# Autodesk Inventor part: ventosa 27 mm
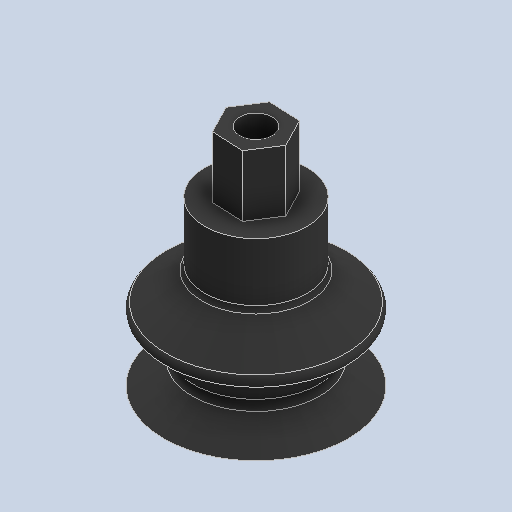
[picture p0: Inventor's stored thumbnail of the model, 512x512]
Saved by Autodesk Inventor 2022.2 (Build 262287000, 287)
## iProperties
Created: 2019-10
Part Number: ventosa 27 mm
Material: Gomma, Silicone
Document SubType Name: Modeling
Designer: 18907419
Density: 1.25 g/cm^3
Appearance: Default
Author: 18907419
Revision Number: ANY
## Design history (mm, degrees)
feature "Solido1"
node "Solido2"
